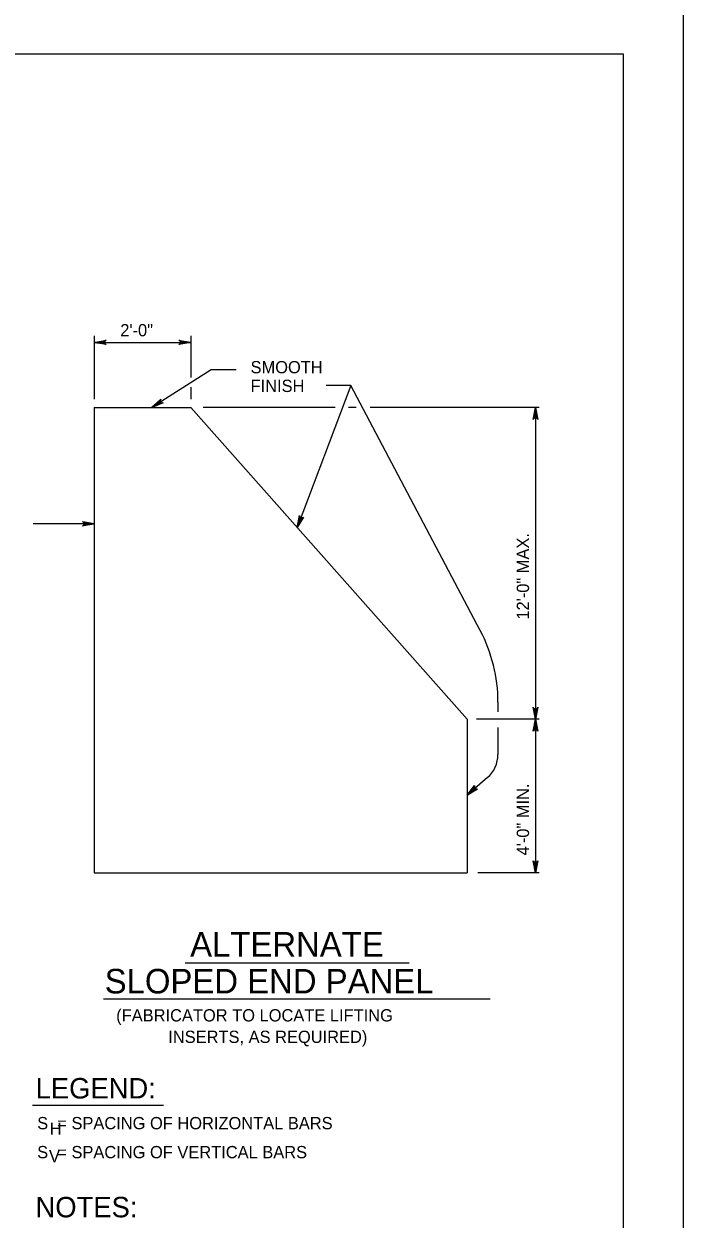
# Model space of a CAD drawing. Extents: x 3385 to 6532, y -616 to 1166.
# Drawn here: x 6119.6 to 6284.3, y 265.2 to 564.2 of the extents above; entities that cross this region are included whole.
import ezdxf

# ---------------------------------------------------------------- set-up
doc = ezdxf.new("R2010")
doc.units = 0
for name, color, linetype in [('1', 7, 'Continuous'), ('2', 7, 'Continuous'), ('PLT-BNDY', 7, 'Continuous')]:
    doc.layers.add(name, color=color, linetype=linetype)

msp = doc.modelspace()

# ---------------------------------------------------------------- linework, layer by layer
at = {"layer": '1'}
for p, q in [((6137.17, 486.14), (6137.17, 470.3)), ((6137.17, 484.52), (6161.32, 484.52)), ((6161.32, 486.14), (6161.32, 475.7)), ((6166.42, 477.69), (6151.56, 468.25)), ((6172.61, 477.69), (6166.42, 477.69)), ((6161.32, 473.36), (6161.32, 470.3)), ((6201.3, 473.72), (6187.9, 438.21)), ((6201.3, 473.72), (6195.11, 473.72)), ((6233.65, 412.43), (6201.3, 473.72)), ((6137.17, 468.25), (6137.17, 351.85)), ((6137.17, 468.25), (6161.32, 468.25)), ((6161.32, 468.25), (6230.35, 390.25)), ((6197.42, 468.25), (6164.41, 468.25)), ((6202.66, 468.25), (6200.67, 468.25)), ((6248.36, 468.25), (6206.14, 468.25)), ((6247.46, 468.25), (6247.46, 390.25)), ((6137.17, 439.13), (6121.88, 439.13)), ((6238.08, 394.51), (6238.08, 392.1)), ((6230.35, 390.25), (6230.35, 351.85)), ((6248.36, 390.25), (6232.72, 390.25)), ((6247.46, 390.25), (6247.46, 351.85)), ((6238.08, 388.19), (6238.08, 381.46)), ((6235.42, 375.64), (6230.35, 371.28)), ((6137.17, 351.85), (6230.35, 351.85)), ((6248.36, 351.85), (6233.07, 351.85)), ((6159.9, 329.32), (6215.85, 329.32)), ((6139.45, 320.31), (6236.11, 320.31)), ((6121.71, 293.75), (6154.5, 293.75))]:
    msp.add_line(p, q, dxfattribs=at)
for points in [[(6137.17, 484.52), (6140.15, 485.08), (6139.92, 484.92), (6139.8, 484.72), (6139.77, 484.52), (6139.8, 484.32), (6139.92, 484.12), (6140.15, 483.97), (6137.17, 484.52), (6139.92, 484.12), (6139.8, 484.32), (6137.17, 484.52), (6139.77, 484.52), (6139.8, 484.72), (6137.17, 484.52), (6139.92, 484.92)], [(6161.32, 484.52), (6158.33, 483.97), (6158.56, 484.12), (6158.68, 484.32), (6158.72, 484.52), (6158.68, 484.72), (6158.56, 484.92), (6158.33, 485.08), (6161.32, 484.52), (6158.56, 484.92), (6158.68, 484.72), (6161.32, 484.52), (6158.72, 484.52), (6158.68, 484.32), (6161.32, 484.52), (6158.56, 484.12)], [(6151.56, 468.25), (6153.78, 470.32), (6153.73, 470.19), (6153.67, 470.06), (6153.68, 469.95), (6153.68, 469.83), (6153.72, 469.74), (6153.76, 469.64), (6153.83, 469.57), (6153.89, 469.49), (6154, 469.44), (6154.1, 469.39), (6154.24, 469.38), (6154.38, 469.38), (6151.56, 468.25), (6154.24, 469.38), (6154.1, 469.39), (6151.56, 468.25), (6154, 469.44), (6153.89, 469.49), (6151.56, 468.25), (6153.83, 469.57), (6153.76, 469.64), (6151.56, 468.25), (6153.72, 469.74), (6153.68, 469.83), (6151.56, 468.25), (6153.68, 469.95), (6153.67, 470.06), (6151.56, 468.25), (6153.73, 470.19)], [(6247.46, 468.25), (6248.02, 465.27), (6247.94, 465.38), (6247.86, 465.5), (6247.76, 465.56), (6247.66, 465.62), (6247.56, 465.63), (6247.46, 465.65), (6247.36, 465.63), (6247.26, 465.62), (6247.16, 465.56), (6247.06, 465.5), (6246.98, 465.38), (6246.9, 465.27), (6247.46, 468.25), (6246.98, 465.38), (6247.06, 465.5), (6247.46, 468.25), (6247.16, 465.56), (6247.26, 465.62), (6247.46, 468.25), (6247.36, 465.63), (6247.46, 465.65), (6247.46, 468.25), (6247.56, 465.63), (6247.66, 465.62), (6247.46, 468.25), (6247.76, 465.56), (6247.86, 465.5), (6247.46, 468.25), (6247.94, 465.38)], [(6137.17, 439.13), (6134.19, 438.57), (6134.3, 438.65), (6134.42, 438.73), (6134.48, 438.83), (6134.54, 438.93), (6134.55, 439.03), (6134.57, 439.13), (6134.55, 439.23), (6134.54, 439.33), (6134.48, 439.43), (6134.42, 439.53), (6134.3, 439.61), (6134.19, 439.69), (6137.17, 439.13), (6134.3, 439.61), (6134.42, 439.53), (6137.17, 439.13), (6134.48, 439.43), (6134.54, 439.33), (6137.17, 439.13), (6134.55, 439.23), (6134.57, 439.13), (6137.17, 439.13), (6134.55, 439.03), (6134.54, 438.93), (6137.17, 439.13), (6134.48, 438.83), (6134.42, 438.73), (6137.17, 439.13), (6134.3, 438.65)], [(6187.9, 438.21), (6188.43, 441.2), (6188.47, 441.06), (6188.5, 440.93), (6188.57, 440.83), (6188.65, 440.74), (6188.73, 440.69), (6188.82, 440.64), (6188.92, 440.62), (6189.02, 440.6), (6189.14, 440.62), (6189.25, 440.64), (6189.36, 440.72), (6189.48, 440.8), (6187.9, 438.21), (6189.36, 440.72), (6189.25, 440.64), (6187.9, 438.21), (6189.14, 440.62), (6189.02, 440.6), (6187.9, 438.21), (6188.92, 440.62), (6188.82, 440.64), (6187.9, 438.21), (6188.73, 440.69), (6188.65, 440.74), (6187.9, 438.21), (6188.57, 440.83), (6188.5, 440.93), (6187.9, 438.21), (6188.47, 441.06)], [(6247.46, 390.25), (6246.9, 393.23), (6246.98, 393.12), (6247.06, 393), (6247.16, 392.94), (6247.26, 392.88), (6247.36, 392.87), (6247.46, 392.85), (6247.56, 392.87), (6247.66, 392.88), (6247.76, 392.94), (6247.86, 393), (6247.94, 393.12), (6248.02, 393.23), (6247.46, 390.25), (6247.94, 393.12), (6247.86, 393), (6247.46, 390.25), (6247.76, 392.94), (6247.66, 392.88), (6247.46, 390.25), (6247.56, 392.87), (6247.46, 392.85), (6247.46, 390.25), (6247.36, 392.87), (6247.26, 392.88), (6247.46, 390.25), (6247.16, 392.94), (6247.06, 393), (6247.46, 390.25), (6246.98, 393.12)], [(6247.46, 390.25), (6248.02, 387.27), (6247.86, 387.5), (6247.66, 387.61), (6247.46, 387.65), (6247.26, 387.61), (6247.06, 387.5), (6246.9, 387.27), (6247.46, 390.25), (6247.06, 387.5), (6247.26, 387.61), (6247.46, 390.25), (6247.46, 387.65), (6247.66, 387.61), (6247.46, 390.25), (6247.86, 387.5)], [(6230.35, 371.28), (6232.24, 373.65), (6232.21, 373.51), (6232.17, 373.38), (6232.19, 373.26), (6232.21, 373.15), (6232.27, 373.06), (6232.32, 372.97), (6232.4, 372.91), (6232.47, 372.84), (6232.59, 372.81), (6232.7, 372.77), (6232.83, 372.78), (6232.97, 372.8), (6230.35, 371.28), (6232.83, 372.78), (6232.7, 372.77), (6230.35, 371.28), (6232.59, 372.81), (6232.47, 372.84), (6230.35, 371.28), (6232.4, 372.91), (6232.32, 372.97), (6230.35, 371.28), (6232.27, 373.06), (6232.21, 373.15), (6230.35, 371.28), (6232.19, 373.26), (6232.17, 373.38), (6230.35, 371.28), (6232.21, 373.51)], [(6247.46, 351.85), (6246.9, 354.83), (6247.06, 354.6), (6247.26, 354.48), (6247.46, 354.45), (6247.66, 354.48), (6247.86, 354.6), (6248.02, 354.83), (6247.46, 351.85), (6247.86, 354.6), (6247.66, 354.48), (6247.46, 351.85), (6247.46, 354.45), (6247.26, 354.48), (6247.46, 351.85), (6247.06, 354.6)]]:
    msp.add_lwpolyline(points, dxfattribs=at)
for centre, radius, start, end in [((6199.68, 394.51), 38.4, 0, 27.8204), ((6230.4, 381.46), 7.68, 310.7343, 0)]:
    msp.add_arc(centre, radius, start, end, dxfattribs=at)
at = {"layer": '2'}
for p, q in [((5483.34, 556.69), (6269.34, 556.69)), ((6269.34, 556.69), (6269.34, -7.31))]:
    msp.add_line(p, q, dxfattribs=at)
at = {"layer": 'PLT-BNDY'}
msp.add_lwpolyline([(5443.34, 571.69), (6284.34, 571.69), (6284.34, -22.31), (5443.34, -22.31)], close=True, dxfattribs=at)

# ---------------------------------------------------------------- texts
at = {"layer": '1'}
for s, height, p in [('2\'-0"', 3.072, (6143.66, 486.04)), ('SMOOTH', 3.072, (6176.23, 476.79)), ('FINISH', 3.072, (6176.23, 472.11)), ('ALTERNATE', 6.144, (6161.13, 330.87)), ('SLOPED END PANEL', 6.144, (6139.77, 321.66)), ('(FABRICATOR TO LOCATE LIFTING', 3.072, (6142.65, 314.65)), ('INSERTS, AS REQUIRED)', 3.072, (6155.66, 309.27)), ('LEGEND:', 5.117, (6122.51, 295.38)), ('S  = SPACING OF HORIZONTAL BARS', 3.072, (6122.9, 287.68)), ('H', 3.07, (6126.05, 286.3)), ('S  = SPACING OF VERTICAL BARS', 3.072, (6122.9, 280.43)), ('V', 3.07, (6125.85, 279.41)), ('NOTES:', 5.117, (6122.48, 265.65))]:
    msp.add_text(s, height=height, dxfattribs=at).set_placement(p)
for s, height, p in [('12\'-0" MAX.', 3.0721, (6245.84, 415.17)), ('4\'-0" MIN.', 3.072, (6245.84, 356.18))]:
    msp.add_text(s, height=height, rotation=90, dxfattribs=at).set_placement(p)

doc.saveas('drawing.dxf')
